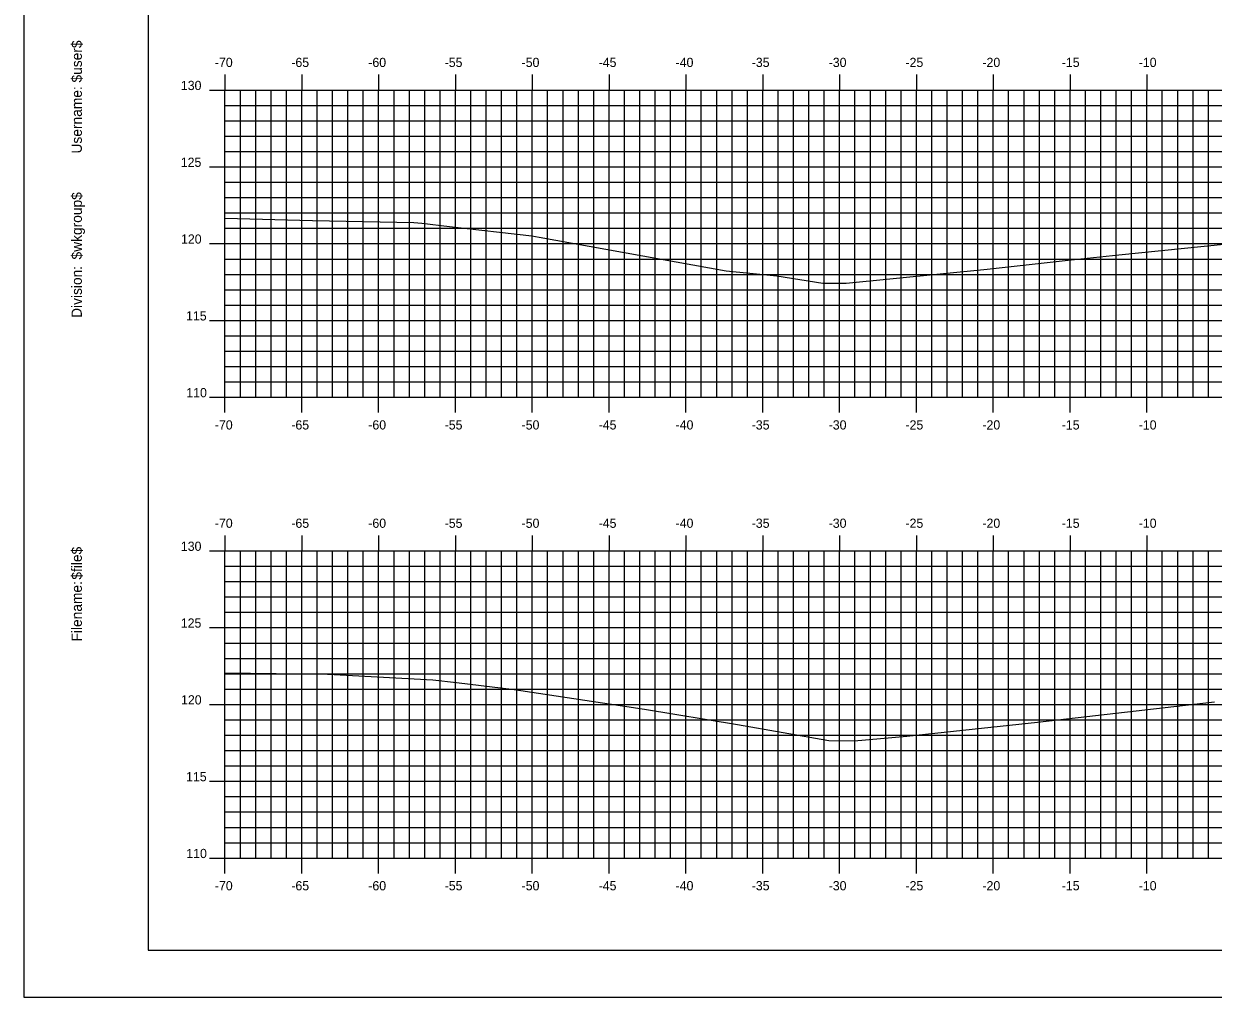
# Model space of a CAD drawing. Extents: x 852847 to 853019, y 365624 to 365734.
# Drawn here: x 852847.2 to 852924.6, y 365624 to 365687.3 of the extents above; entities that cross this region are included whole.
import ezdxf

# ---------------------------------------------------------------- set-up
doc = ezdxf.new("R2010")
doc.units = 0
for name, color, linetype in [('BORDER', 7, 'Continuous'), ('H_V ANNOTATION', 7, 'Continuous'), ('MAJOR', 7, 'Continuous'), ('MINOR', 7, 'Continuous'), ('PLOT BOUNDARY', 7, 'Continuous'), ('S_Roadway_Centerline', 7, 'Continuous')]:
    doc.layers.add(name, color=color, linetype=linetype)

msp = doc.modelspace()

# ---------------------------------------------------------------- linework, layer by layer
at = {"layer": 'BORDER'}
msp.add_lwpolyline([(852855.305, 365627.027), (853015.305, 365627.027), (853015.305, 365732.027), (852855.305, 365732.027)], close=True, dxfattribs=at)
at = {"layer": 'MAJOR'}
for p, q in [((852860.305, 365684.029), (852860.305, 365683.027)), ((852865.305, 365684.029), (852865.305, 365683.027)), ((852870.305, 365684.029), (852870.305, 365683.027)), ((852875.305, 365684.029), (852875.305, 365683.027)), ((852880.305, 365684.029), (852880.305, 365683.027)), ((852885.305, 365684.029), (852885.305, 365683.027)), ((852890.305, 365684.029), (852890.305, 365683.027)), ((852895.305, 365684.029), (852895.305, 365683.027)), ((852900.305, 365684.029), (852900.305, 365683.027)), ((852905.305, 365684.029), (852905.305, 365683.027)), ((852910.305, 365684.029), (852910.305, 365683.027)), ((852915.305, 365684.029), (852915.305, 365683.027)), ((852920.305, 365684.029), (852920.305, 365683.027)), ((852859.303, 365683.027), (852860.305, 365683.027)), ((852860.305, 365683.027), (853000.305, 365683.027)), ((852860.305, 365663.027), (852860.305, 365683.027)), ((852860.305, 365663.027), (852860.305, 365683.027)), ((852860.305, 365683.027), (853000.305, 365683.027)), ((852865.305, 365663.027), (852865.305, 365683.027)), ((852870.305, 365663.027), (852870.305, 365683.027)), ((852875.305, 365663.027), (852875.305, 365683.027)), ((852880.305, 365663.027), (852880.305, 365683.027)), ((852885.305, 365663.027), (852885.305, 365683.027)), ((852890.305, 365663.027), (852890.305, 365683.027)), ((852895.305, 365663.027), (852895.305, 365683.027)), ((852900.305, 365663.027), (852900.305, 365683.027)), ((852905.305, 365663.027), (852905.305, 365683.027)), ((852910.305, 365663.027), (852910.305, 365683.027)), ((852915.305, 365663.027), (852915.305, 365683.027)), ((852920.305, 365663.027), (852920.305, 365683.027)), ((852859.303, 365678.027), (852860.305, 365678.027)), ((852860.305, 365678.027), (853000.305, 365678.027)), ((852859.303, 365673.027), (852860.305, 365673.027)), ((852860.305, 365673.027), (853000.305, 365673.027)), ((852859.303, 365668.027), (852860.305, 365668.027)), ((852860.305, 365668.027), (853000.305, 365668.027)), ((852859.303, 365663.027), (852860.305, 365663.027)), ((852860.305, 365663.027), (853000.305, 365663.027)), ((852860.305, 365663.027), (853000.305, 365663.027)), ((852860.305, 365662.025), (852860.305, 365663.027)), ((852865.305, 365662.025), (852865.305, 365663.027)), ((852870.305, 365662.025), (852870.305, 365663.027)), ((852875.305, 365662.025), (852875.305, 365663.027)), ((852880.305, 365662.025), (852880.305, 365663.027)), ((852885.305, 365662.025), (852885.305, 365663.027)), ((852890.305, 365662.025), (852890.305, 365663.027)), ((852895.305, 365662.025), (852895.305, 365663.027)), ((852900.305, 365662.025), (852900.305, 365663.027)), ((852905.305, 365662.025), (852905.305, 365663.027)), ((852910.305, 365662.025), (852910.305, 365663.027)), ((852915.305, 365662.025), (852915.305, 365663.027)), ((852920.305, 365662.025), (852920.305, 365663.027)), ((852860.305, 365654.029), (852860.305, 365653.027)), ((852865.305, 365654.029), (852865.305, 365653.027)), ((852870.305, 365654.029), (852870.305, 365653.027)), ((852875.305, 365654.029), (852875.305, 365653.027)), ((852880.305, 365654.029), (852880.305, 365653.027)), ((852885.305, 365654.029), (852885.305, 365653.027)), ((852890.305, 365654.029), (852890.305, 365653.027)), ((852895.305, 365654.029), (852895.305, 365653.027)), ((852900.305, 365654.029), (852900.305, 365653.027)), ((852905.305, 365654.029), (852905.305, 365653.027)), ((852910.305, 365654.029), (852910.305, 365653.027)), ((852915.305, 365654.029), (852915.305, 365653.027)), ((852920.305, 365654.029), (852920.305, 365653.027)), ((852859.303, 365653.027), (852860.305, 365653.027)), ((852860.305, 365653.027), (853000.305, 365653.027)), ((852860.305, 365633.027), (852860.305, 365653.027)), ((852860.305, 365633.027), (852860.305, 365653.027)), ((852860.305, 365653.027), (853000.305, 365653.027)), ((852865.305, 365633.027), (852865.305, 365653.027)), ((852870.305, 365633.027), (852870.305, 365653.027)), ((852875.305, 365633.027), (852875.305, 365653.027)), ((852880.305, 365633.027), (852880.305, 365653.027)), ((852885.305, 365633.027), (852885.305, 365653.027)), ((852890.305, 365633.027), (852890.305, 365653.027)), ((852895.305, 365633.027), (852895.305, 365653.027)), ((852900.305, 365633.027), (852900.305, 365653.027)), ((852905.305, 365633.027), (852905.305, 365653.027)), ((852910.305, 365633.027), (852910.305, 365653.027)), ((852915.305, 365633.027), (852915.305, 365653.027)), ((852920.305, 365633.027), (852920.305, 365653.027)), ((852859.303, 365648.027), (852860.305, 365648.027)), ((852860.305, 365648.027), (853000.305, 365648.027)), ((852859.303, 365643.027), (852860.305, 365643.027)), ((852860.305, 365643.027), (853000.305, 365643.027)), ((852859.303, 365638.027), (852860.305, 365638.027)), ((852860.305, 365638.027), (853000.305, 365638.027)), ((852859.303, 365633.027), (852860.305, 365633.027)), ((852860.305, 365633.027), (853000.305, 365633.027)), ((852860.305, 365633.027), (853000.305, 365633.027)), ((852860.305, 365632.025), (852860.305, 365633.027)), ((852865.305, 365632.025), (852865.305, 365633.027)), ((852870.305, 365632.025), (852870.305, 365633.027)), ((852875.305, 365632.025), (852875.305, 365633.027)), ((852880.305, 365632.025), (852880.305, 365633.027)), ((852885.305, 365632.025), (852885.305, 365633.027)), ((852890.305, 365632.025), (852890.305, 365633.027)), ((852895.305, 365632.025), (852895.305, 365633.027)), ((852900.305, 365632.025), (852900.305, 365633.027)), ((852905.305, 365632.025), (852905.305, 365633.027)), ((852910.305, 365632.025), (852910.305, 365633.027)), ((852915.305, 365632.025), (852915.305, 365633.027)), ((852920.305, 365632.025), (852920.305, 365633.027))]:
    msp.add_line(p, q, dxfattribs=at)
at = {"layer": 'MINOR'}
for p, q in [((852861.305, 365663.027), (852861.305, 365683.027)), ((852862.305, 365663.027), (852862.305, 365683.027)), ((852863.305, 365663.027), (852863.305, 365683.027)), ((852864.305, 365663.027), (852864.305, 365683.027)), ((852866.305, 365663.027), (852866.305, 365683.027)), ((852867.305, 365663.027), (852867.305, 365683.027)), ((852868.305, 365663.027), (852868.305, 365683.027)), ((852869.305, 365663.027), (852869.305, 365683.027)), ((852871.305, 365663.027), (852871.305, 365683.027)), ((852872.305, 365663.027), (852872.305, 365683.027)), ((852873.305, 365663.027), (852873.305, 365683.027)), ((852874.305, 365663.027), (852874.305, 365683.027)), ((852876.305, 365663.027), (852876.305, 365683.027)), ((852877.305, 365663.027), (852877.305, 365683.027)), ((852878.305, 365663.027), (852878.305, 365683.027)), ((852879.305, 365663.027), (852879.305, 365683.027)), ((852881.305, 365663.027), (852881.305, 365683.027)), ((852882.305, 365663.027), (852882.305, 365683.027)), ((852883.305, 365663.027), (852883.305, 365683.027)), ((852884.305, 365663.027), (852884.305, 365683.027)), ((852886.305, 365663.027), (852886.305, 365683.027)), ((852887.305, 365663.027), (852887.305, 365683.027)), ((852888.305, 365663.027), (852888.305, 365683.027)), ((852889.305, 365663.027), (852889.305, 365683.027)), ((852891.305, 365663.027), (852891.305, 365683.027)), ((852892.305, 365663.027), (852892.305, 365683.027)), ((852893.305, 365663.027), (852893.305, 365683.027)), ((852894.305, 365663.027), (852894.305, 365683.027)), ((852896.305, 365663.027), (852896.305, 365683.027)), ((852897.305, 365663.027), (852897.305, 365683.027)), ((852898.305, 365663.027), (852898.305, 365683.027)), ((852899.305, 365663.027), (852899.305, 365683.027)), ((852901.305, 365663.027), (852901.305, 365683.027)), ((852902.305, 365663.027), (852902.305, 365683.027)), ((852903.305, 365663.027), (852903.305, 365683.027)), ((852904.305, 365663.027), (852904.305, 365683.027)), ((852906.305, 365663.027), (852906.305, 365683.027)), ((852907.305, 365663.027), (852907.305, 365683.027)), ((852908.305, 365663.027), (852908.305, 365683.027)), ((852909.305, 365663.027), (852909.305, 365683.027)), ((852911.305, 365663.027), (852911.305, 365683.027)), ((852912.305, 365663.027), (852912.305, 365683.027)), ((852913.305, 365663.027), (852913.305, 365683.027)), ((852914.305, 365663.027), (852914.305, 365683.027)), ((852916.305, 365663.027), (852916.305, 365683.027)), ((852917.305, 365663.027), (852917.305, 365683.027)), ((852918.305, 365663.027), (852918.305, 365683.027)), ((852919.305, 365663.027), (852919.305, 365683.027)), ((852921.305, 365663.027), (852921.305, 365683.027)), ((852922.305, 365663.027), (852922.305, 365683.027)), ((852923.305, 365663.027), (852923.305, 365683.027)), ((852924.305, 365663.027), (852924.305, 365683.027)), ((852860.305, 365682.027), (853000.305, 365682.027)), ((852860.305, 365682.027), (852861.307, 365682.027)), ((852860.305, 365681.027), (853000.305, 365681.027)), ((852860.305, 365681.027), (852861.307, 365681.027)), ((852860.305, 365680.027), (853000.305, 365680.027)), ((852860.305, 365680.027), (852861.307, 365680.027)), ((852860.305, 365679.027), (853000.305, 365679.027)), ((852860.305, 365679.027), (852861.307, 365679.027)), ((852860.305, 365677.027), (853000.305, 365677.027)), ((852860.305, 365677.027), (852861.307, 365677.027)), ((852860.305, 365676.027), (853000.305, 365676.027)), ((852860.305, 365676.027), (852861.307, 365676.027)), ((852860.305, 365675.027), (853000.305, 365675.027)), ((852860.305, 365675.027), (852861.307, 365675.027)), ((852860.305, 365674.027), (853000.305, 365674.027)), ((852860.305, 365674.027), (852861.307, 365674.027)), ((852860.305, 365672.027), (853000.305, 365672.027)), ((852860.305, 365672.027), (852861.307, 365672.027)), ((852860.305, 365671.027), (853000.305, 365671.027)), ((852860.305, 365671.027), (852861.307, 365671.027)), ((852860.305, 365670.027), (853000.305, 365670.027)), ((852860.305, 365670.027), (852861.307, 365670.027)), ((852860.305, 365669.027), (853000.305, 365669.027)), ((852860.305, 365669.027), (852861.307, 365669.027)), ((852860.305, 365667.027), (853000.305, 365667.027)), ((852860.305, 365667.027), (852861.307, 365667.027)), ((852860.305, 365666.027), (853000.305, 365666.027)), ((852860.305, 365666.027), (852861.307, 365666.027)), ((852860.305, 365665.027), (853000.305, 365665.027)), ((852860.305, 365665.027), (852861.307, 365665.027)), ((852860.305, 365664.027), (853000.305, 365664.027)), ((852860.305, 365664.027), (852861.307, 365664.027)), ((852861.305, 365633.027), (852861.305, 365653.027)), ((852862.305, 365633.027), (852862.305, 365653.027)), ((852863.305, 365633.027), (852863.305, 365653.027)), ((852864.305, 365633.027), (852864.305, 365653.027)), ((852866.305, 365633.027), (852866.305, 365653.027)), ((852867.305, 365633.027), (852867.305, 365653.027)), ((852868.305, 365633.027), (852868.305, 365653.027)), ((852869.305, 365633.027), (852869.305, 365653.027)), ((852871.305, 365633.027), (852871.305, 365653.027)), ((852872.305, 365633.027), (852872.305, 365653.027)), ((852873.305, 365633.027), (852873.305, 365653.027)), ((852874.305, 365633.027), (852874.305, 365653.027)), ((852876.305, 365633.027), (852876.305, 365653.027)), ((852877.305, 365633.027), (852877.305, 365653.027)), ((852878.305, 365633.027), (852878.305, 365653.027)), ((852879.305, 365633.027), (852879.305, 365653.027)), ((852881.305, 365633.027), (852881.305, 365653.027)), ((852882.305, 365633.027), (852882.305, 365653.027)), ((852883.305, 365633.027), (852883.305, 365653.027)), ((852884.305, 365633.027), (852884.305, 365653.027)), ((852886.305, 365633.027), (852886.305, 365653.027)), ((852887.305, 365633.027), (852887.305, 365653.027)), ((852888.305, 365633.027), (852888.305, 365653.027)), ((852889.305, 365633.027), (852889.305, 365653.027)), ((852891.305, 365633.027), (852891.305, 365653.027)), ((852892.305, 365633.027), (852892.305, 365653.027)), ((852893.305, 365633.027), (852893.305, 365653.027)), ((852894.305, 365633.027), (852894.305, 365653.027)), ((852896.305, 365633.027), (852896.305, 365653.027)), ((852897.305, 365633.027), (852897.305, 365653.027)), ((852898.305, 365633.027), (852898.305, 365653.027)), ((852899.305, 365633.027), (852899.305, 365653.027)), ((852901.305, 365633.027), (852901.305, 365653.027)), ((852902.305, 365633.027), (852902.305, 365653.027)), ((852903.305, 365633.027), (852903.305, 365653.027)), ((852904.305, 365633.027), (852904.305, 365653.027)), ((852906.305, 365633.027), (852906.305, 365653.027)), ((852907.305, 365633.027), (852907.305, 365653.027)), ((852908.305, 365633.027), (852908.305, 365653.027)), ((852909.305, 365633.027), (852909.305, 365653.027)), ((852911.305, 365633.027), (852911.305, 365653.027)), ((852912.305, 365633.027), (852912.305, 365653.027)), ((852913.305, 365633.027), (852913.305, 365653.027)), ((852914.305, 365633.027), (852914.305, 365653.027)), ((852916.305, 365633.027), (852916.305, 365653.027)), ((852917.305, 365633.027), (852917.305, 365653.027)), ((852918.305, 365633.027), (852918.305, 365653.027)), ((852919.305, 365633.027), (852919.305, 365653.027)), ((852921.305, 365633.027), (852921.305, 365653.027)), ((852922.305, 365633.027), (852922.305, 365653.027)), ((852923.305, 365633.027), (852923.305, 365653.027)), ((852924.305, 365633.027), (852924.305, 365653.027)), ((852860.305, 365652.027), (853000.305, 365652.027)), ((852860.305, 365652.027), (852861.307, 365652.027)), ((852860.305, 365651.027), (853000.305, 365651.027)), ((852860.305, 365651.027), (852861.307, 365651.027)), ((852860.305, 365650.027), (853000.305, 365650.027)), ((852860.305, 365650.027), (852861.307, 365650.027)), ((852860.305, 365649.027), (853000.305, 365649.027)), ((852860.305, 365649.027), (852861.307, 365649.027)), ((852860.305, 365647.027), (853000.305, 365647.027)), ((852860.305, 365647.027), (852861.307, 365647.027)), ((852860.305, 365646.027), (853000.305, 365646.027)), ((852860.305, 365646.027), (852861.307, 365646.027)), ((852860.305, 365645.027), (853000.305, 365645.027)), ((852860.305, 365645.027), (852861.307, 365645.027)), ((852860.305, 365644.027), (853000.305, 365644.027)), ((852860.305, 365644.027), (852861.307, 365644.027)), ((852860.305, 365642.027), (853000.305, 365642.027)), ((852860.305, 365642.027), (852861.307, 365642.027)), ((852860.305, 365641.027), (853000.305, 365641.027)), ((852860.305, 365641.027), (852861.307, 365641.027)), ((852860.305, 365640.027), (853000.305, 365640.027)), ((852860.305, 365640.027), (852861.307, 365640.027)), ((852860.305, 365639.027), (853000.305, 365639.027)), ((852860.305, 365639.027), (852861.307, 365639.027)), ((852860.305, 365637.027), (853000.305, 365637.027)), ((852860.305, 365637.027), (852861.307, 365637.027)), ((852860.305, 365636.027), (853000.305, 365636.027)), ((852860.305, 365636.027), (852861.307, 365636.027)), ((852860.305, 365635.027), (853000.305, 365635.027)), ((852860.305, 365635.027), (852861.307, 365635.027)), ((852860.305, 365634.027), (853000.305, 365634.027)), ((852860.305, 365634.027), (852861.307, 365634.027))]:
    msp.add_line(p, q, dxfattribs=at)
at = {"layer": 'PLOT BOUNDARY'}
msp.add_lwpolyline([(852847.212, 365623.968), (853017.212, 365623.968), (853017.212, 365733.968), (852847.212, 365733.968)], close=True, dxfattribs=at)
at = {"layer": 'S_Roadway_Centerline'}
for points in [[(852860.305, 365674.692), (852866.003, 365674.542), (852872.589, 365674.4), (852873.115, 365674.363), (852874.912, 365674.147), (852880.281, 365673.546), (852880.761, 365673.455), (852892.915, 365671.266), (852896.212, 365670.935), (852899.218, 365670.456), (852900.735, 365670.452), (852909.897, 365671.361), (852915.185, 365671.959), (852918.469, 365672.292), (852926.799, 365673.154)], [(852860.305, 365645.09), (852866.983, 365644.996), (852866.992, 365644.996), (852873.831, 365644.632), (852875.366, 365644.453), (852879.129, 365643.995), (852887.599, 365642.72), (852893.651, 365641.719), (852899.61, 365640.691), (852901.249, 365640.658), (852904.677, 365640.957), (852913.178, 365641.884), (852924.71, 365643.199)]]:
    msp.add_lwpolyline(points, dxfattribs=at)

# ---------------------------------------------------------------- texts
at = {"layer": 'BORDER'}
for s, p in [('$user$', (852850.99, 365683.518)), ('Username:', (852850.99, 365678.895)), ('$wkgroup$', (852850.99, 365671.996)), ('Division:', (852850.99, 365668.193)), ('$file$', (852850.99, 365651.152)), ('Filename:', (852850.99, 365647.125))]:
    msp.add_text(s, height=0.6696, rotation=90, dxfattribs=at).set_placement(p)
at = {"layer": 'H_V ANNOTATION'}
for s, p in [('-70', (852859.647, 365684.527)), ('-65', (852864.623, 365684.527)), ('-60', (852869.631, 365684.527)), ('-55', (852874.601, 365684.527)), ('-50', (852879.609, 365684.527)), ('-45', (852884.623, 365684.527)), ('-40', (852889.631, 365684.527)), ('-35', (852894.585, 365684.527)), ('-30', (852899.593, 365684.527)), ('-25', (852904.59, 365684.527)), ('-20', (852909.598, 365684.527)), ('-15', (852914.762, 365684.527)), ('-10', (852919.77, 365684.527)), ('130', (852857.435, 365683.027)), ('125', (852857.429, 365678.027)), ('120', (852857.445, 365673.027)), ('115', (852857.772, 365668.027)), ('110', (852857.788, 365663.027)), ('-70', (852859.647, 365660.927)), ('-65', (852864.623, 365660.927)), ('-60', (852869.631, 365660.927)), ('-55', (852874.601, 365660.927)), ('-50', (852879.609, 365660.927)), ('-45', (852884.623, 365660.927)), ('-40', (852889.631, 365660.927)), ('-35', (852894.585, 365660.927)), ('-30', (852899.593, 365660.927)), ('-25', (852904.59, 365660.927)), ('-20', (852909.598, 365660.927)), ('-15', (852914.762, 365660.927)), ('-10', (852919.77, 365660.927)), ('-70', (852859.647, 365654.527)), ('-65', (852864.623, 365654.527)), ('-60', (852869.631, 365654.527)), ('-55', (852874.601, 365654.527)), ('-50', (852879.609, 365654.527)), ('-45', (852884.623, 365654.527)), ('-40', (852889.631, 365654.527)), ('-35', (852894.585, 365654.527)), ('-30', (852899.593, 365654.527)), ('-25', (852904.59, 365654.527)), ('-20', (852909.598, 365654.527)), ('-15', (852914.762, 365654.527)), ('-10', (852919.77, 365654.527)), ('130', (852857.435, 365653.027)), ('125', (852857.429, 365648.027)), ('120', (852857.445, 365643.027)), ('115', (852857.772, 365638.027)), ('110', (852857.788, 365633.027)), ('-70', (852859.647, 365630.927)), ('-65', (852864.623, 365630.927)), ('-60', (852869.631, 365630.927)), ('-55', (852874.601, 365630.927)), ('-50', (852879.609, 365630.927)), ('-45', (852884.623, 365630.927)), ('-40', (852889.631, 365630.927)), ('-35', (852894.585, 365630.927)), ('-30', (852899.593, 365630.927)), ('-25', (852904.59, 365630.927)), ('-20', (852909.598, 365630.927)), ('-15', (852914.762, 365630.927)), ('-10', (852919.77, 365630.927))]:
    msp.add_text(s, height=0.6, dxfattribs=at).set_placement(p)
at = {"layer": 'MAJOR'}
for p in [(852860.3, 365663.027), (852860.3, 365633.027)]:
    msp.add_text('-', height=0.006, dxfattribs=at).set_placement(p)

doc.saveas('drawing.dxf')
